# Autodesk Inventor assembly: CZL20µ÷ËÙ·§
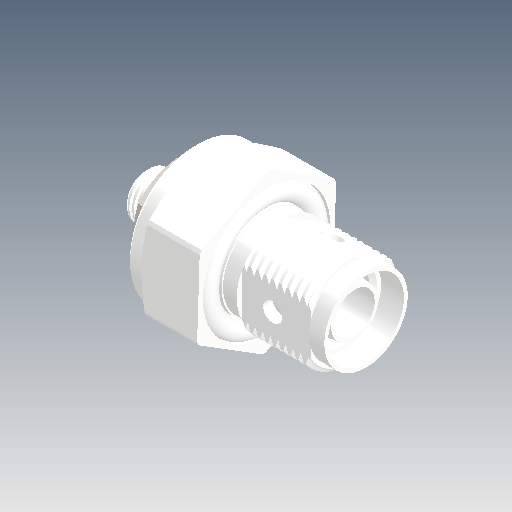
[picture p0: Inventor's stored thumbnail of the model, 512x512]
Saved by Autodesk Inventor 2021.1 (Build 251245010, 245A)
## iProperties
Created: 2021-05
Part Number: CZL20µ÷ËÙ·§
Document SubType Name: Assembly
Designer: user
Author: user
Revision Number: ÈÎºÎ
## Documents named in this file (4)
- D:\Vault_2016\Projekty\Clamptek\Hydraulic\CHLC\CHLC-40\Inventor\CHLC-FAMT40\CZL20µ÷ËÙ·§.iam
- D:\Vault_2016\Projekty\Clamptek\Hydraulic\CHLC\CHLC-40\Inventor\CHLC-FAMT40\20·§Ìå.ipt
- D:\Vault_2016\Projekty\Clamptek\Hydraulic\CHLC\CHLC-40\Inventor\CHLC-FAMT40\20µ÷ËÙ¸Ë.ipt
- D:\Vault_2016\Projekty\Clamptek\Hydraulic\CHLC\CHLC-40\Inventor\CHLC-FAMT40\hex thin nuts-grades ab-chamfered gb(GB_FASTENER_NUT_STNAB M6-S).ipt
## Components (3 placed, 3 different names)
1. 20·§Ìå_19
2. 20µ÷ËÙ¸Ë_20
3. hex thin nuts-grades ab-chamfered gb(GB_FASTENER_NUT_STNAB M6-S)_21
